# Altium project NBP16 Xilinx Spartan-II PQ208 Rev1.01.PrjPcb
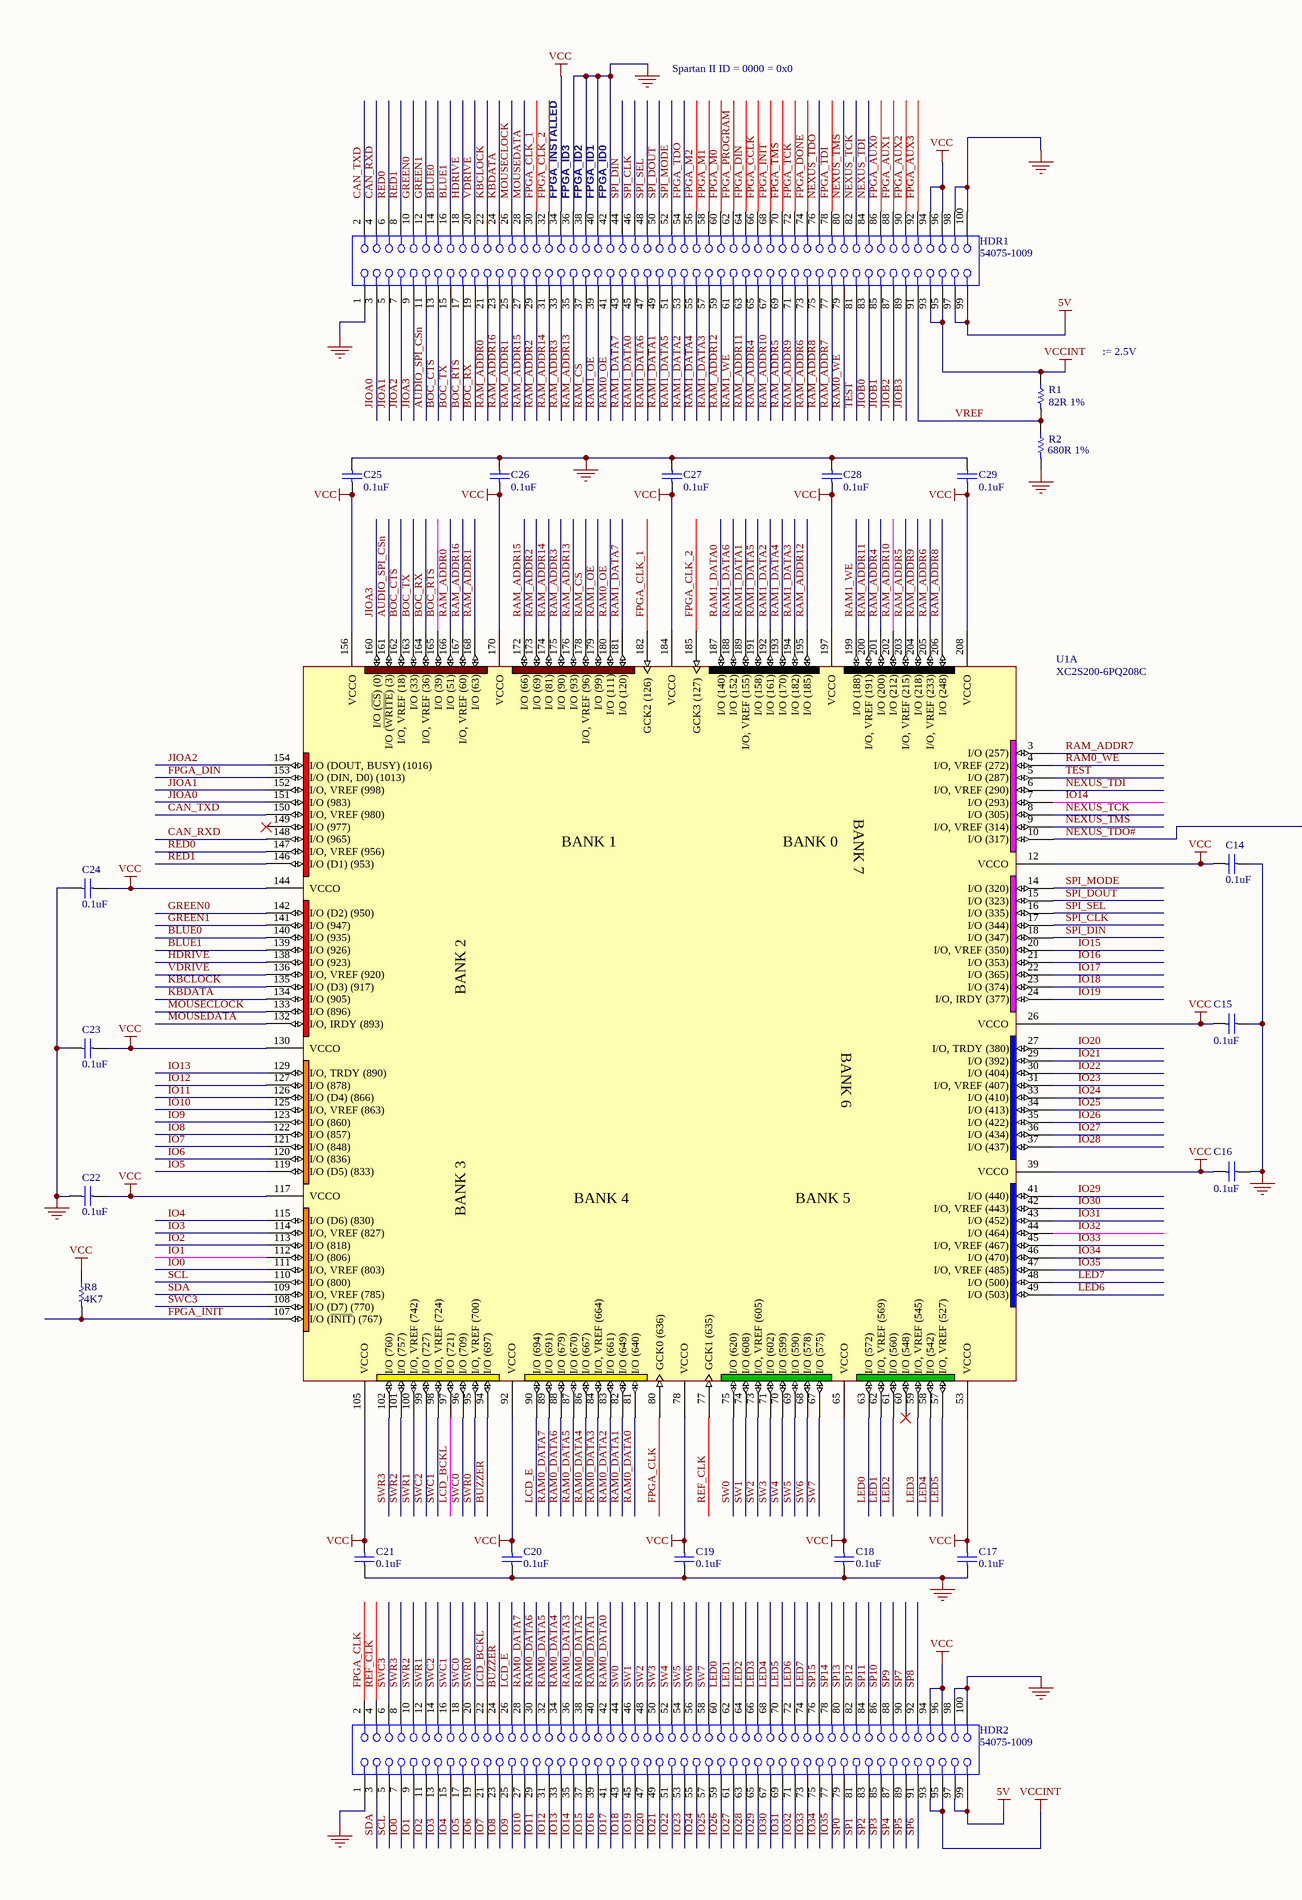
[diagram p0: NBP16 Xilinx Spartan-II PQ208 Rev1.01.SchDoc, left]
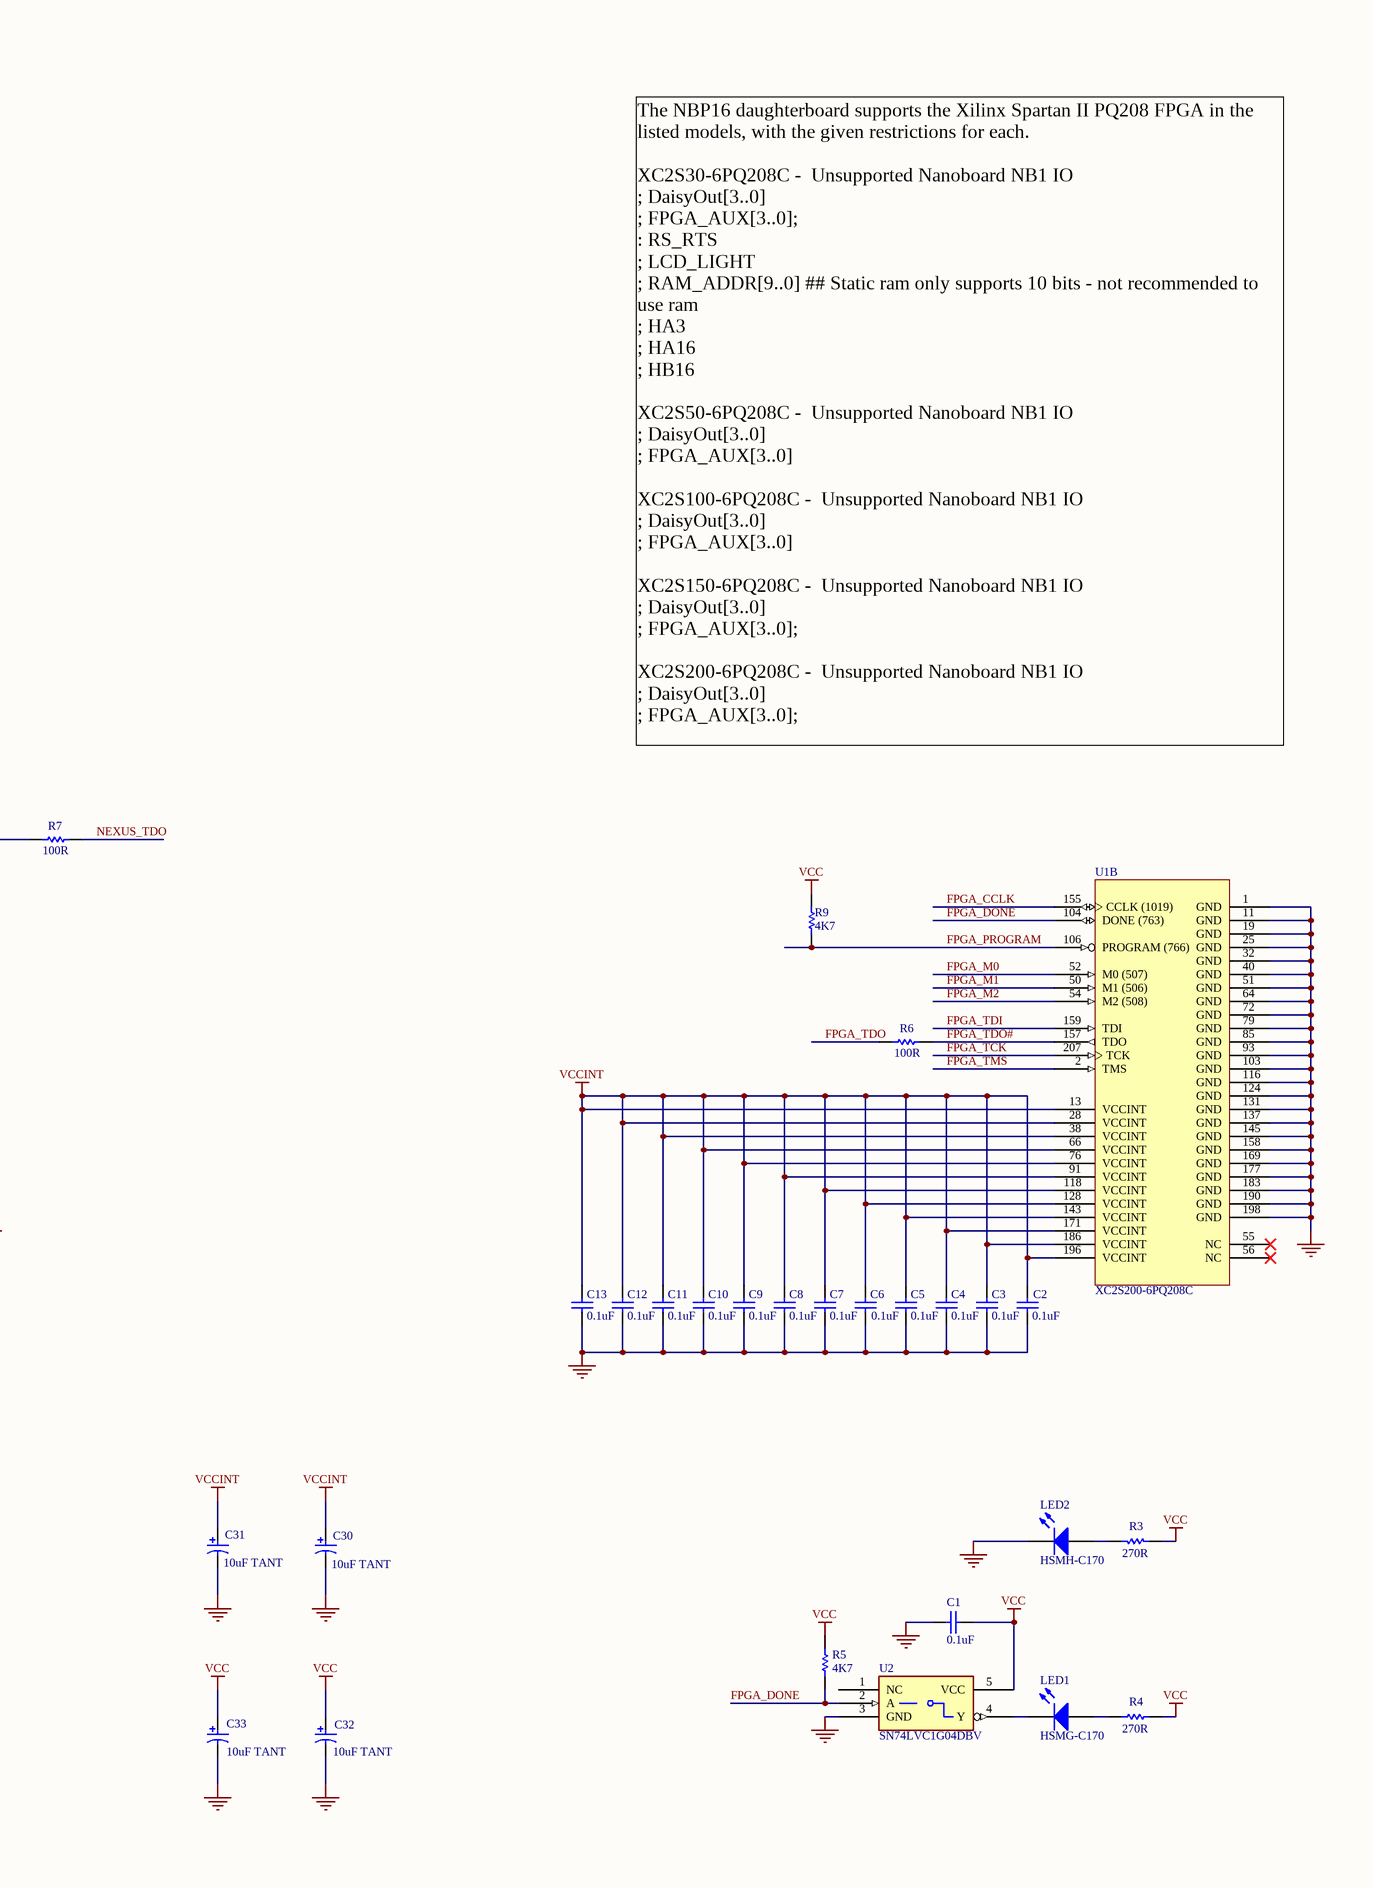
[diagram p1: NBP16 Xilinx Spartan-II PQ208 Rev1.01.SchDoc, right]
1 sheet, 48 parts. Net scope: global (net labels, ports and power ports of the same name join across sheets).
Board file: NBP16 Xilinx Spartan-II PQ208 Rev1.01.PcbDoc

## Sheet NBP16 Xilinx Spartan-II PQ208 Rev1.01.SchDoc: Xilinx Spartan II Daughter Board
size A2; Organization: Altium Limited; Address1: L3, 12a Rodborough Rd; Address2: Frenchs Forest; Address3: NSW; Address4: Australia 2086; DocumentNumber: 1; Revision: 1.01; SheetNumber: 1; SheetTotal: 1

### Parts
C1  0.1uF  [CC2012-0805]
C2  0.1uF  [CC1608-0603]
C3  0.1uF  [CC1608-0603]
C4  0.1uF  [CC1608-0603]
C5  0.1uF  [CC1608-0603]
C6  0.1uF  [CC1608-0603]
C7  0.1uF  [CC1608-0603]
C8  0.1uF  [CC1608-0603]
C9  0.1uF  [CC1608-0603]
C10  0.1uF  [CC1608-0603]
C11  0.1uF  [CC1608-0603]
C12  0.1uF  [CC1608-0603]
C13  0.1uF  [CC1608-0603]
C14  0.1uF  [CC1608-0603]
C15  0.1uF  [CC1608-0603]
C16  0.1uF  [CC1608-0603]
C17  0.1uF  [CC1608-0603]
C18  0.1uF  [CC1608-0603]
C19  0.1uF  [CC1608-0603]
C20  0.1uF  [CC1608-0603]
C21  0.1uF  [CC1608-0603]
C22  0.1uF  [CC1608-0603]
C23  0.1uF  [CC1608-0603]
C24  0.1uF  [CC1608-0603]
C25  0.1uF  [CC1608-0603]
C26  0.1uF  [CC1608-0603]
C27  0.1uF  [CC1608-0603]
C28  0.1uF  [CC1608-0603]
C29  0.1uF  [CC1608-0603]
C30  10uF TANT  [MCCT-B]
C31  10uF TANT  [MCCT-B]
C32  10uF TANT  [MCCT-B]
C33  10uF TANT  [MCCT-B]
HDR1  54075-1009  [54075]
HDR2  54075-1009  [54075]
LED1  HSMG-C170  [SMD _LED]
LED2  HSMH-C170  [SMD _LED]
R1  82R 1%  [CC2012-0805]
R2  680R 1%  [CC2012-0805]
R3  270R  [CC2012-0805]
R4  270R  [CC2012-0805]
R5  4K7  [CC2012-0805]
R6  100R  [CC2012-0805]
R7  100R  [CC2012-0805]
R8  4K7  [CC2012-0805]
R9  4K7  [CC2012-0805]
U1  XC2S200-6PQ208C  [F-QFP28X28-G208/P.5N]  (parts A,B of 2)
U2  SN74LVC1G04DBV  [SO-G5/P.95]

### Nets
5V: HDR1.97 HDR1.99 HDR2.97 HDR2.99
GND: C1.1 C2.2 C3.2 C4.2 C5.2 C6.2 C7.2 C8.2 C9.2 C10.2 C11.2 C12.2 C13.2 C14.2 C15.2 C16.2 C17.1 C18.1 C19.1 C20.1 C21.1 C22.2 C23.2 C24.2 C25.1 C26.1 C27.1 C28.1 C29.1 C30.2 C31.2 C32.2 C33.2 HDR1.1 HDR1.36 HDR1.38 HDR1.40 HDR1.42 HDR1.98 HDR1.100 HDR2.1 HDR2.98 HDR2.100 LED2.2(K) R2.2 U1.1(GND) U1.11(GND) U1.19(GND) U1.25(GND) U1.32(GND) U1.40(GND) U1.51(GND) U1.64(GND) U1.72(GND) U1.79(GND) U1.85(GND) U1.93(GND) U1.103(GND) U1.116(GND) U1.124(GND) U1.131(GND) U1.137(GND) U1.145(GND) U1.158(GND) U1.169(GND) U1.177(GND) U1.183(GND) U1.190(GND) U1.198(GND) U2.3(GND)
VCC: C1.2 C14.1 C15.1 C16.1 C17.2 C18.2 C19.2 C20.2 C21.2 C22.1 C23.1 C24.1 C25.2 C26.2 C27.2 C28.2 C29.2 C32.1 C33.1 HDR1.34 HDR1.94 HDR1.96 HDR2.94 HDR2.96 R3.1 R4.2 R5.1 R8.1 R9.1 U1.12(VCCO) U1.26(VCCO) U1.39(VCCO) U1.53(VCCO) U1.65(VCCO) U1.78(VCCO) U1.92(VCCO) U1.105(VCCO) U1.117(VCCO) U1.130(VCCO) U1.144(VCCO) U1.156(VCCO) U1.170(VCCO) U1.184(VCCO) U1.197(VCCO) U1.208(VCCO) U2.5(VCC)
VCCINT: C2.1 C3.1 C4.1 C5.1 C6.1 C7.1 C8.1 C9.1 C10.1 C11.1 C12.1 C13.1 C30.1 C31.1 HDR1.93 HDR1.95 HDR2.93 HDR2.95 R1.1 U1.13(VCCINT) U1.28(VCCINT) U1.38(VCCINT) U1.66(VCCINT) U1.76(VCCINT) U1.91(VCCINT) U1.118(VCCINT) U1.128(VCCINT) U1.143(VCCINT) U1.171(VCCINT) U1.186(VCCINT) U1.196(VCCINT)
AUDIO_SPI_CSn: HDR1.11 U1.161(I/O_(~{WRITE})_(3))
BLUE0: HDR1.14 U1.140(I/O_(935))
BLUE1: HDR1.16 U1.139(I/O_(926))
BOC_CTS: HDR1.13 U1.162(I/O,_VREF_(18))
BOC_RTS: HDR1.17 U1.165(I/O_(39))
BOC_RX: HDR1.19 U1.164(I/O,_VREF_(36))
BOC_TX: HDR1.15 U1.163(I/O_(33))
BUZZER: HDR2.24 U1.94(I/O_(697))
CAN_RXD: HDR1.4 U1.148(I/O_(965))
CAN_TXD: HDR1.2 U1.150(I/O,_VREF_(980))
FPGA_AUX0: HDR1.86
FPGA_AUX1: HDR1.88
FPGA_AUX2: HDR1.90
FPGA_AUX3: HDR1.92
FPGA_CCLK: HDR1.66 U1.155(CCLK_(1019))
FPGA_CLK: HDR2.2 U1.80(GCK0_(636))
FPGA_CLK_1: HDR1.30 U1.182(GCK2_(126))
FPGA_CLK_2: HDR1.32 U1.185(GCK3_(127))
FPGA_DIN: HDR1.64 U1.153(I/O_(DIN,_D0)_(1013))
FPGA_DONE: HDR1.74 R5.2 U1.104(DONE_(763)) U2.2(A)
FPGA_INIT: HDR1.68 R8.2 U1.107(I/O_(~{INIT})_(767))
FPGA_M0: HDR1.60 U1.52(M0_(507))
FPGA_M1: HDR1.58 U1.50(M1_(506))
FPGA_M2: HDR1.56 U1.54(M2_(508))
FPGA_PROGRAM: HDR1.62 R9.2 U1.106(PROGRAM_(766))
FPGA_TCK: HDR1.72 U1.207(TCK)
FPGA_TDI: HDR1.78 U1.159(TDI)
FPGA_TDO: HDR1.54 R6.1
FPGA_TDO#: R6.2 U1.157(TDO)
FPGA_TMS: HDR1.70 U1.2(TMS)
GREEN0: HDR1.10 U1.142(I/O_(D2)_(950))
GREEN1: HDR1.12 U1.141(I/O_(947))
HDRIVE: HDR1.18 U1.138(I/O_(923))
IO0: HDR2.7 U1.111(I/O,_VREF_(803))
IO1: HDR2.9 U1.112(I/O_(806))
IO2: HDR2.11 U1.113(I/O_(818))
IO3: HDR2.13 U1.114(I/O,_VREF_(827))
IO4: HDR2.15 U1.115(I/O_(D6)_(830))
IO5: HDR2.17 U1.119(I/O_(D5)_(833))
IO6: HDR2.19 U1.120(I/O_(836))
IO7: HDR2.21 U1.121(I/O_(848))
IO8: HDR2.23 U1.122(I/O_(857))
IO9: HDR2.25 U1.123(I/O_(860))
IO10: HDR2.27 U1.125(I/O,_VREF_(863))
IO11: HDR2.29 U1.126(I/O_(D4)_(866))
IO12: HDR2.31 U1.127(I/O_(878))
IO13: HDR2.33 U1.129(I/O,_TRDY_(890))
IO14: HDR2.35 U1.7(I/O_(293))
IO15: HDR2.37 U1.20(I/O,_VREF_(350))
IO16: HDR2.39 U1.21(I/O_(353))
IO17: HDR2.41 U1.22(I/O_(365))
IO18: HDR2.43 U1.23(I/O_(374))
IO19: HDR2.45 U1.24(I/O,_IRDY_(377))
IO20: HDR2.47 U1.27(I/O,_TRDY_(380))
IO21: HDR2.49 U1.29(I/O_(392))
IO22: HDR2.51 U1.30(I/O_(404))
IO23: HDR2.53 U1.31(I/O,_VREF_(407))
IO24: HDR2.55 U1.33(I/O_(410))
IO25: HDR2.57 U1.34(I/O_(413))
IO26: HDR2.59 U1.35(I/O_(422))
IO27: HDR2.61 U1.36(I/O_(434))
IO28: HDR2.63 U1.37(I/O_(437))
IO29: HDR2.65 U1.41(I/O_(440))
IO30: HDR2.67 U1.42(I/O,_VREF_(443))
IO31: HDR2.69 U1.43(I/O_(452))
IO32: HDR2.71 U1.44(I/O_(464))
IO33: HDR2.73 U1.45(I/O,_VREF_(467))
IO34: HDR2.75 U1.46(I/O_(470))
IO35: HDR2.77 U1.47(I/O,_VREF_(485))
JIOA0: HDR1.3 U1.151(I/O_(983))
JIOA1: HDR1.5 U1.152(I/O,_VREF_(998))
JIOA2: HDR1.7 U1.154(I/O_(DOUT,_BUSY)_(1016))
JIOA3: HDR1.9 U1.160(I/O_(~{CS})_(0))
JIOB0: HDR1.83
JIOB1: HDR1.85
JIOB2: HDR1.87
JIOB3: HDR1.89
KBCLOCK: HDR1.22 U1.135(I/O_(D3)_(917))
KBDATA: HDR1.24 U1.134(I/O_(905))
LCD_BCKL: HDR2.22 U1.97(I/O_(721))
LCD_E: HDR2.26 U1.90(I/O_(694))
LED0: HDR2.60 U1.63(I/O_(572))
LED1: HDR2.62 U1.62(I/O,_VREF_(569))
LED2: HDR2.64 U1.61(I/O_(560))
LED3: HDR2.66 U1.59(I/O,_VREF_(545))
LED4: HDR2.68 U1.58(I/O_(542))
LED5: HDR2.70 U1.57(I/O,_VREF_(527))
LED6: HDR2.72 U1.49(I/O_(503))
LED7: HDR2.74 U1.48(I/O_(500))
MOUSECLOCK: HDR1.26 U1.133(I/O_(896))
MOUSEDATA: HDR1.28 U1.132(I/O,_IRDY_(893))
NEXUS_TCK: HDR1.82 U1.8(I/O_(305))
NEXUS_TDI: HDR1.84 U1.6(I/O,_VREF_(290))
NEXUS_TDO: HDR1.76 R7.2
NEXUS_TDO#: R7.1 U1.10(I/O_(317))
NEXUS_TMS: HDR1.80 U1.9(I/O,_VREF_(314))
RAM0_DATA0: HDR2.42 U1.81(I/O_(640))
RAM0_DATA1: HDR2.40 U1.82(I/O_(649))
RAM0_DATA2: HDR2.38 U1.83(I/O_(661))
RAM0_DATA3: HDR2.36 U1.84(I/O,_VREF_(664))
RAM0_DATA4: HDR2.34 U1.86(I/O_(667))
RAM0_DATA5: HDR2.32 U1.87(I/O_(670))
RAM0_DATA6: HDR2.30 U1.88(I/O_(679))
RAM0_DATA7: HDR2.28 U1.89(I/O_(691))
RAM0_OE: HDR1.41 U1.180(I/O_(111))
RAM0_WE: HDR1.79 U1.4(I/O,_VREF_(272))
RAM1_DATA0: HDR1.45 U1.187(I/O_(140))
RAM1_DATA1: HDR1.49 U1.189(I/O,_VREF_(155))
RAM1_DATA2: HDR1.53 U1.192(I/O_(161))
RAM1_DATA3: HDR1.57 U1.194(I/O_(182))
RAM1_DATA4: HDR1.55 U1.193(I/O_(170))
RAM1_DATA5: HDR1.51 U1.191(I/O_(158))
RAM1_DATA6: HDR1.47 U1.188(I/O_(152))
RAM1_DATA7: HDR1.43 U1.181(I/O_(120))
RAM1_OE: HDR1.39 U1.179(I/O_(99))
RAM1_WE: HDR1.61 U1.199(I/O_(188))
RAM_ADDR0: HDR1.21 U1.166(I/O_(51))
RAM_ADDR1: HDR1.25 U1.168(I/O_(63))
RAM_ADDR2: HDR1.29 U1.173(I/O_(69))
RAM_ADDR3: HDR1.33 U1.175(I/O_(90))
RAM_ADDR4: HDR1.65 U1.201(I/O_(200))
RAM_ADDR5: HDR1.69 U1.203(I/O,_VREF_(215))
RAM_ADDR6: HDR1.73 U1.205(I/O,_VREF_(233))
RAM_ADDR7: HDR1.77 U1.3(I/O_(257))
RAM_ADDR8: HDR1.75 U1.206(I/O_(248))
RAM_ADDR9: HDR1.71 U1.204(I/O_(218))
RAM_ADDR10: HDR1.67 U1.202(I/O_(212))
RAM_ADDR11: HDR1.63 U1.200(I/O,_VREF_(191))
RAM_ADDR12: HDR1.59 U1.195(I/O_(185))
RAM_ADDR13: HDR1.35 U1.176(I/O_(93))
RAM_ADDR14: HDR1.31 U1.174(I/O_(81))
RAM_ADDR15: HDR1.27 U1.172(I/O_(66))
RAM_ADDR16: HDR1.23 U1.167(I/O,_VREF_(60))
RAM_CS: HDR1.37 U1.178(I/O,_VREF_(96))
RED0: HDR1.6 U1.147(I/O,_VREF_(956))
RED1: HDR1.8 U1.146(I/O_(D1)_(953))
REF_CLK: HDR2.4 U1.77(GCK1_(635))
SCL: HDR2.5 U1.110(I/O_(800))
SDA: HDR2.3 U1.109(I/O,_VREF_(785))
SP0: HDR2.79
SP1: HDR2.81
SP2: HDR2.83
SP3: HDR2.85
SP4: HDR2.87
SP5: HDR2.89
SP6: HDR2.91
SP7: HDR2.90
SP8: HDR2.92
SP9: HDR2.88
SP10: HDR2.86
SP11: HDR2.84
SP12: HDR2.82
SP13: HDR2.80
SP14: HDR2.78
SP15: HDR2.76
SPI_CLK: HDR1.46 U1.17(I/O_(344))
SPI_DIN: HDR1.44 U1.18(I/O_(347))
SPI_DOUT: HDR1.50 U1.15(I/O_(323))
SPI_MODE: HDR1.52 U1.14(I/O_(320))
SPI_SEL: HDR1.48 U1.16(I/O_(335))
SW0: HDR2.44 U1.75(I/O_(620))
SW1: HDR2.46 U1.74(I/O_(608))
SW2: HDR2.48 U1.73(I/O,_VREF_(605))
SW3: HDR2.50 U1.71(I/O_(602))
SW4: HDR2.52 U1.70(I/O_(599))
SW5: HDR2.54 U1.69(I/O_(590))
SW6: HDR2.56 U1.68(I/O_(578))
SW7: HDR2.58 U1.67(I/O_(575))
SWC0: HDR2.18 U1.96(I/O_(709))
SWC1: HDR2.16 U1.98(I/O,_VREF_(724))
SWC2: HDR2.14 U1.99(I/O_(727))
SWC3: HDR2.6 U1.108(I/O_(D7)_(770))
SWR0: HDR2.20 U1.95(I/O,_VREF_(700))
SWR1: HDR2.12 U1.100(I/O,_VREF_(742))
SWR2: HDR2.10 U1.101(I/O_(757))
SWR3: HDR2.8 U1.102(I/O_(760))
TEST: HDR1.81 U1.5(I/O_(287))
VDRIVE: HDR1.20 U1.136(I/O,_VREF_(920))
VREF: HDR1.91 R1.2 R2.1
NetLED1_1: LED1.1(A) R4.1
NetLED1_2: LED1.2(K) U2.4(Y)
NetLED2_1: LED2.1(A) R3.2

Not connected (* = marked no-connect by the designer): U1 55(NC)* 56(NC)* 60(I/O_(548))* 149(I/O_(977))*; U2 1(NC)

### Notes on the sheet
- Spartan II ID = 0000 = 0x0
- (near HDR1) FPGA_INSTALLED
- (near HDR1) FPGA_ID3
- (near HDR1) FPGA_ID2
- (near HDR1) FPGA_ID1
- (near HDR1) FPGA_ID0
- := 2.5V
- The NBP16 daughterboard supports the Xilinx Spartan II PQ208 FPGA in the listed models, with the given restrictions for each.
  XC2S30-6PQ208C -  Unsupported Nanoboard NB1 IO
  ; DaisyOut[3..0]
  ; FPGA_AUX[3..0];
  : RS_RTS
  ; LCD_LIGHT
  ; RAM_ADDR[9..0] ## Static ram only supports 10 bits - not recommended to use ram
  ; HA3
  ; HA16
  ; HB16
  XC2S50-6PQ208C -  Unsupported Nanoboard NB1 IO
  ; DaisyOut[3..0]
  ; FPGA_AUX[3..0]
  XC2S100-6PQ208C -  Unsupported Nanoboard NB1 IO
  ; DaisyOut[3..0]
  ; FPGA_AUX[3..0]
  XC2S150-6PQ208C -  Unsupported Nanoboard NB1 IO
  ; DaisyOut[3..0]
  ; FPGA_AUX[3..0];
  XC2S200-6PQ208C -  Unsupported Nanoboard NB1 IO
  ; DaisyOut[3..0]
  ; FPGA_AUX[3..0];

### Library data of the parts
C1-C29 = CAP: Capacitor
C30-C33 = CAP_POLAR: Polar Capacitor
HDR1 HDR2 = 54075-1009: Board-to-Board, Docking Station, 0.80mm (.031") Pitch, Shielded Receptacle, Vertical, Ultra Low Profile, SMT; Manufacturer: Molex; Package Information: Latest Revision: Jun-2001; Mating Height: 8.5mm; Voltage: 100V; Current: 0.5A; Contact Resistance: 40mOhm max; PCB Layout: Complies with Manufacturer's Recommendation.
LED1 LED2 = HSMX-C670: Typical RED GaAs SMD LED Agilent make; Manufacturer: Generic Components; Class I: Optoelectronic; Fitted: True
R1-R9 = RES: Resistor
U1 = XC2S200-6PQ208C: Spartan-II 2.5V FPGA, 208-Pin PQFP, Higher Performance, Commercial Grade; Package Information: Latest Revision: ver1.1, Oct-2002; Code - JEDEC: MS-029-FA-1
U2 = SN74AHC1G04DBVR: Manufacturer: TI; Fitted: True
